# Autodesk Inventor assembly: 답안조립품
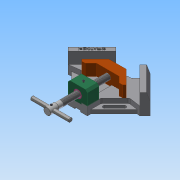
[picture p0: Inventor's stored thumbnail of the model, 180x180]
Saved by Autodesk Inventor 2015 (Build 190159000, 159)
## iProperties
Created: 2020-05
Part Number: 답안조립품
Document SubType Name: Assembly
Designer: LINEART-SSD.D4.16.06
Author: LINEART-SSD.D4.16.06
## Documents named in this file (11)
- C:\Users\LINEART-SSD.D4.16.06\Desktop\700506V1056\답안조립품.iam
- C:\Users\LINEART-SSD.D4.16.06\Desktop\700506V1056\베이스.ipt
- C:\Users\LINEART-SSD.D4.16.06\Desktop\700506V1056\리드스크류.ipt
- C:\Users\LINEART-SSD.D4.16.06\Desktop\700506V1056\부시.ipt
- C:\Users\LINEART-SSD.D4.16.06\Desktop\700506V1056\서포트.ipt
- C:\Users\LINEART-SSD.D4.16.06\Desktop\700506V1056\조.ipt
- C:\Users\LINEART-SSD.D4.16.06\Desktop\700506V1056\핸들.ipt
- C:\Users\LINEART-SSD.D4.16.06\Desktop\700506V1056\멈춤나사 M4x5.ipt
- C:\Users\LINEART-SSD.D4.16.06\Desktop\700506V1056\멈춤나사 M4x10.ipt
- C:\Users\LINEART-SSD.D4.16.06\Desktop\700506V1056\평행 핀 2.5x24.ipt
- C:\Users\LINEART-SSD.D4.16.06\Desktop\700506V1056\볼트 M4x16.ipt
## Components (1 placed, 1 different names)
1. 핸들:1
